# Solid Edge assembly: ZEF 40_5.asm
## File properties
Title: Zylinder
Author: ahadarics
Template: iso metric assembly.asm
Last saved by: ahadarics
Revision: 2
Application: Solid Edge
Username: ahadarics
Dokumentum tartalom típus: 1
Document Number: ZEF 40/5
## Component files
Mutter.par
Profilrohr.par
Kolbenstange.par
Kit_1.par
Kit_2.par
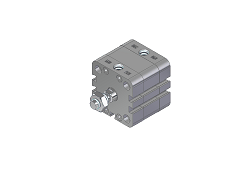
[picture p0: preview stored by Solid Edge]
